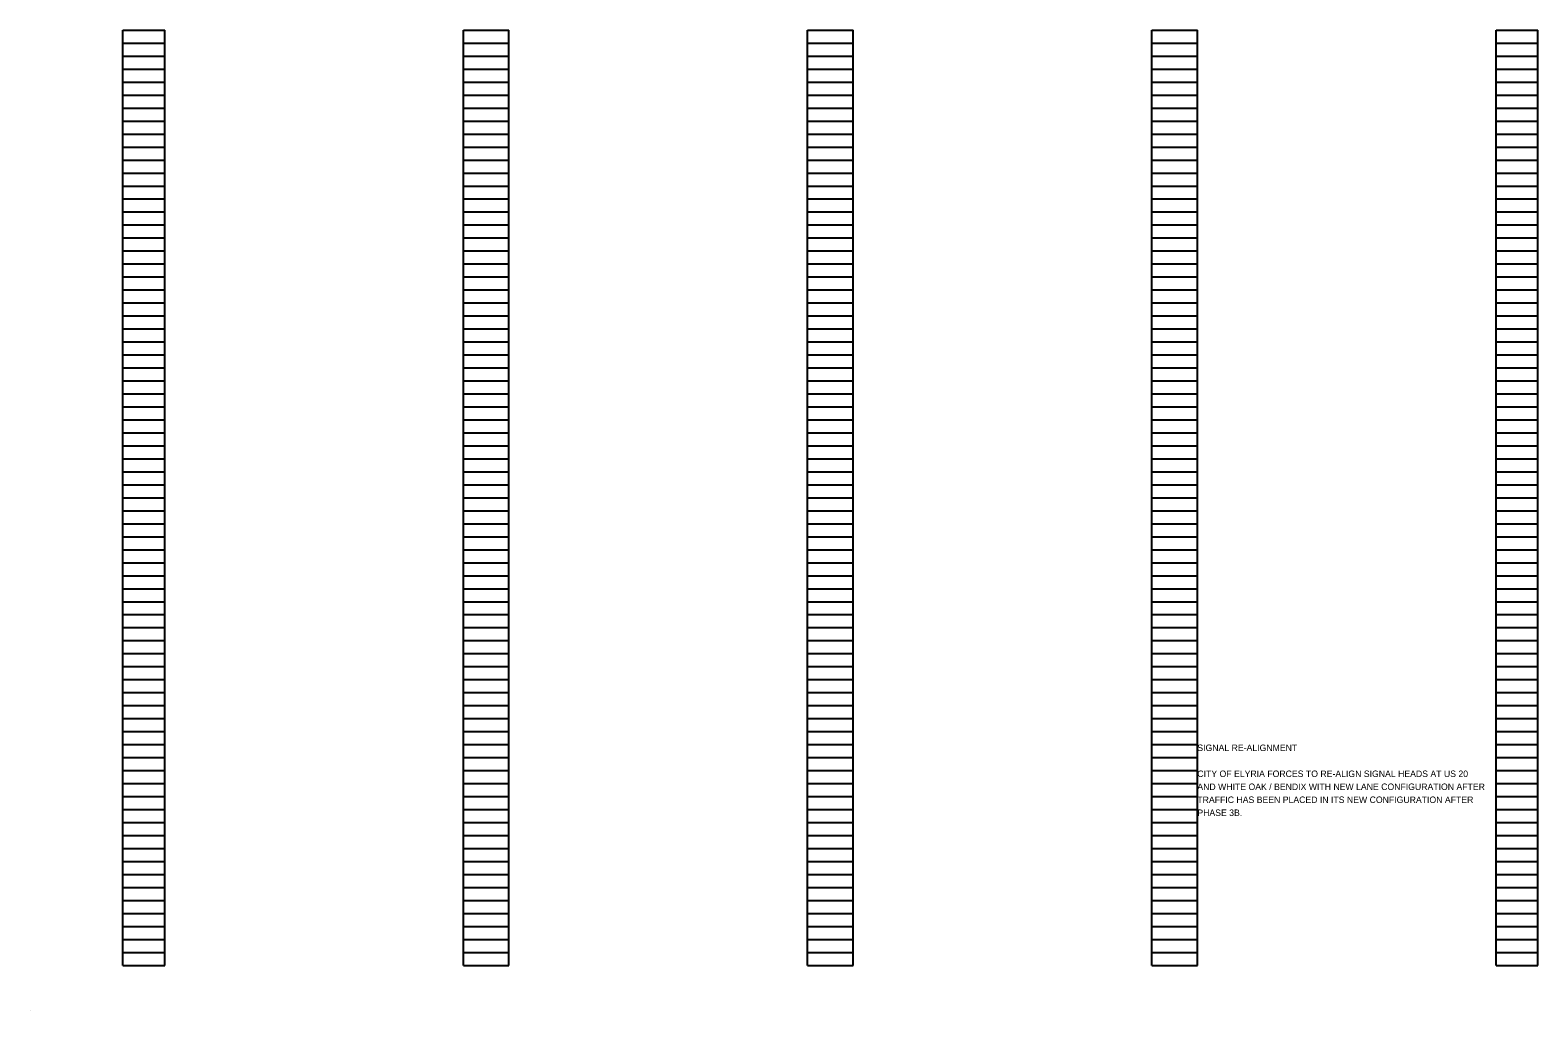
# Model space of a CAD drawing. Extents: x -12.2 to 34.1, y -24.5 to 43.2.
# Drawn here: x 1.62 to 34.12, y -24.51 to -3.37 of the extents above; entities that cross this region are included whole.
import ezdxf

# ---------------------------------------------------------------- set-up
doc = ezdxf.new("R2010")
doc.units = 0
doc.layers.add('SH_Data', color=7, linetype='Continuous')
doc.layers.add('SH_Text', color=7, linetype='Continuous')

msp = doc.modelspace()

# ---------------------------------------------------------------- linework, layer by layer
at = {"layer": 'SH_Data'}
for p, q in [((3.615, -23.528), (3.615, -3.368)), ((3.615, -3.368), (4.515, -3.368)), ((4.515, -23.528), (4.515, -3.368)), ((10.955, -23.528), (10.955, -3.368)), ((10.955, -3.368), (11.935, -3.368)), ((11.935, -23.528), (11.935, -3.368)), ((18.375, -23.528), (18.375, -3.368)), ((18.375, -3.368), (19.355, -3.368)), ((19.355, -23.528), (19.355, -3.368)), ((25.795, -23.528), (25.795, -3.368)), ((25.795, -3.368), (26.775, -3.368)), ((26.775, -23.528), (26.775, -3.368)), ((33.215, -23.528), (33.215, -3.368)), ((33.215, -3.368), (34.115, -3.368)), ((34.115, -23.528), (34.115, -3.368)), ((3.615, -3.648), (4.515, -3.648)), ((10.955, -3.648), (11.935, -3.648)), ((18.375, -3.648), (19.355, -3.648)), ((25.795, -3.648), (26.775, -3.648)), ((33.215, -3.648), (34.115, -3.648)), ((3.615, -3.928), (4.515, -3.928)), ((3.615, -4.208), (4.515, -4.208)), ((10.955, -3.928), (11.935, -3.928)), ((10.955, -4.208), (11.935, -4.208)), ((18.375, -3.928), (19.355, -3.928)), ((18.375, -4.208), (19.355, -4.208)), ((25.795, -3.928), (26.775, -3.928)), ((25.795, -4.208), (26.775, -4.208)), ((33.215, -3.928), (34.115, -3.928)), ((33.215, -4.208), (34.115, -4.208)), ((3.615, -4.488), (4.515, -4.488)), ((10.955, -4.488), (11.935, -4.488)), ((18.375, -4.488), (19.355, -4.488)), ((25.795, -4.488), (26.775, -4.488)), ((33.215, -4.488), (34.115, -4.488)), ((3.615, -4.768), (4.515, -4.768)), ((10.955, -4.768), (11.935, -4.768)), ((18.375, -4.768), (19.355, -4.768)), ((25.795, -4.768), (26.775, -4.768)), ((33.215, -4.768), (34.115, -4.768)), ((3.615, -5.048), (4.515, -5.048)), ((10.955, -5.048), (11.935, -5.048)), ((18.375, -5.048), (19.355, -5.048)), ((25.795, -5.048), (26.775, -5.048)), ((33.215, -5.048), (34.115, -5.048)), ((3.615, -5.328), (4.515, -5.328)), ((10.955, -5.328), (11.935, -5.328)), ((18.375, -5.328), (19.355, -5.328)), ((25.795, -5.328), (26.775, -5.328)), ((33.215, -5.328), (34.115, -5.328)), ((3.615, -5.608), (4.515, -5.608)), ((10.955, -5.608), (11.935, -5.608)), ((18.375, -5.608), (19.355, -5.608)), ((25.795, -5.608), (26.775, -5.608)), ((33.215, -5.608), (34.115, -5.608)), ((3.615, -5.888), (4.515, -5.888)), ((3.615, -6.168), (4.515, -6.168)), ((10.955, -5.888), (11.935, -5.888)), ((10.955, -6.168), (11.935, -6.168)), ((18.375, -5.888), (19.355, -5.888)), ((18.375, -6.168), (19.355, -6.168)), ((25.795, -5.888), (26.775, -5.888)), ((25.795, -6.168), (26.775, -6.168)), ((33.215, -5.888), (34.115, -5.888)), ((33.215, -6.168), (34.115, -6.168)), ((3.615, -6.448), (4.515, -6.448)), ((10.955, -6.448), (11.935, -6.448)), ((18.375, -6.448), (19.355, -6.448)), ((25.795, -6.448), (26.775, -6.448)), ((33.215, -6.448), (34.115, -6.448)), ((3.615, -6.728), (4.515, -6.728)), ((10.955, -6.728), (11.935, -6.728)), ((18.375, -6.728), (19.355, -6.728)), ((25.795, -6.728), (26.775, -6.728)), ((33.215, -6.728), (34.115, -6.728)), ((3.615, -7.008), (4.515, -7.008)), ((10.955, -7.008), (11.935, -7.008)), ((18.375, -7.008), (19.355, -7.008)), ((25.795, -7.008), (26.775, -7.008)), ((33.215, -7.008), (34.115, -7.008)), ((3.615, -7.288), (4.515, -7.288)), ((10.955, -7.288), (11.935, -7.288)), ((18.375, -7.288), (19.355, -7.288)), ((25.795, -7.288), (26.775, -7.288)), ((33.215, -7.288), (34.115, -7.288)), ((3.615, -7.568), (4.515, -7.568)), ((10.955, -7.568), (11.935, -7.568)), ((18.375, -7.568), (19.355, -7.568)), ((25.795, -7.568), (26.775, -7.568)), ((33.215, -7.568), (34.115, -7.568)), ((3.615, -7.848), (4.515, -7.848)), ((10.955, -7.848), (11.935, -7.848)), ((18.375, -7.848), (19.355, -7.848)), ((25.795, -7.848), (26.775, -7.848)), ((33.215, -7.848), (34.115, -7.848)), ((3.615, -8.128), (4.515, -8.128)), ((3.615, -8.408), (4.515, -8.408)), ((10.955, -8.128), (11.935, -8.128)), ((10.955, -8.408), (11.935, -8.408)), ((18.375, -8.128), (19.355, -8.128)), ((18.375, -8.408), (19.355, -8.408)), ((25.795, -8.128), (26.775, -8.128)), ((25.795, -8.408), (26.775, -8.408)), ((33.215, -8.128), (34.115, -8.128)), ((33.215, -8.408), (34.115, -8.408)), ((3.615, -8.688), (4.515, -8.688)), ((10.955, -8.688), (11.935, -8.688)), ((18.375, -8.688), (19.355, -8.688)), ((25.795, -8.688), (26.775, -8.688)), ((33.215, -8.688), (34.115, -8.688)), ((3.615, -8.968), (4.515, -8.968)), ((10.955, -8.968), (11.935, -8.968)), ((18.375, -8.968), (19.355, -8.968)), ((25.795, -8.968), (26.775, -8.968)), ((33.215, -8.968), (34.115, -8.968)), ((3.615, -9.248), (4.515, -9.248)), ((10.955, -9.248), (11.935, -9.248)), ((18.375, -9.248), (19.355, -9.248)), ((25.795, -9.248), (26.775, -9.248)), ((33.215, -9.248), (34.115, -9.248)), ((3.615, -9.528), (4.515, -9.528)), ((10.955, -9.528), (11.935, -9.528)), ((18.375, -9.528), (19.355, -9.528)), ((25.795, -9.528), (26.775, -9.528)), ((33.215, -9.528), (34.115, -9.528)), ((3.615, -9.808), (4.515, -9.808)), ((10.955, -9.808), (11.935, -9.808)), ((18.375, -9.808), (19.355, -9.808)), ((25.795, -9.808), (26.775, -9.808)), ((33.215, -9.808), (34.115, -9.808)), ((3.615, -10.088), (4.515, -10.088)), ((3.615, -10.368), (4.515, -10.368)), ((10.955, -10.088), (11.935, -10.088)), ((10.955, -10.368), (11.935, -10.368)), ((18.375, -10.088), (19.355, -10.088)), ((18.375, -10.368), (19.355, -10.368)), ((25.795, -10.088), (26.775, -10.088)), ((25.795, -10.368), (26.775, -10.368)), ((33.215, -10.088), (34.115, -10.088)), ((33.215, -10.368), (34.115, -10.368)), ((3.615, -10.648), (4.515, -10.648)), ((10.955, -10.648), (11.935, -10.648)), ((18.375, -10.648), (19.355, -10.648)), ((25.795, -10.648), (26.775, -10.648)), ((33.215, -10.648), (34.115, -10.648)), ((3.615, -10.928), (4.515, -10.928)), ((10.955, -10.928), (11.935, -10.928)), ((18.375, -10.928), (19.355, -10.928)), ((25.795, -10.928), (26.775, -10.928)), ((33.215, -10.928), (34.115, -10.928)), ((3.615, -11.208), (4.515, -11.208)), ((10.955, -11.208), (11.935, -11.208)), ((18.375, -11.208), (19.355, -11.208)), ((25.795, -11.208), (26.775, -11.208)), ((33.215, -11.208), (34.115, -11.208)), ((3.615, -11.488), (4.515, -11.488)), ((10.955, -11.488), (11.935, -11.488)), ((18.375, -11.488), (19.355, -11.488)), ((25.795, -11.488), (26.775, -11.488)), ((33.215, -11.488), (34.115, -11.488)), ((3.615, -11.768), (4.515, -11.768)), ((10.955, -11.768), (11.935, -11.768)), ((18.375, -11.768), (19.355, -11.768)), ((25.795, -11.768), (26.775, -11.768)), ((33.215, -11.768), (34.115, -11.768)), ((3.615, -12.048), (4.515, -12.048)), ((3.615, -12.328), (4.515, -12.328)), ((10.955, -12.048), (11.935, -12.048)), ((10.955, -12.328), (11.935, -12.328)), ((18.375, -12.048), (19.355, -12.048)), ((18.375, -12.328), (19.355, -12.328)), ((25.795, -12.048), (26.775, -12.048)), ((25.795, -12.328), (26.775, -12.328)), ((33.215, -12.048), (34.115, -12.048)), ((33.215, -12.328), (34.115, -12.328)), ((3.615, -12.608), (4.515, -12.608)), ((10.955, -12.608), (11.935, -12.608)), ((18.375, -12.608), (19.355, -12.608)), ((25.795, -12.608), (26.775, -12.608)), ((33.215, -12.608), (34.115, -12.608)), ((3.615, -12.888), (4.515, -12.888)), ((10.955, -12.888), (11.935, -12.888)), ((18.375, -12.888), (19.355, -12.888)), ((25.795, -12.888), (26.775, -12.888)), ((33.215, -12.888), (34.115, -12.888)), ((3.615, -13.168), (4.515, -13.168)), ((10.955, -13.168), (11.935, -13.168)), ((18.375, -13.168), (19.355, -13.168)), ((25.795, -13.168), (26.775, -13.168)), ((33.215, -13.168), (34.115, -13.168)), ((3.615, -13.448), (4.515, -13.448)), ((10.955, -13.448), (11.935, -13.448)), ((18.375, -13.448), (19.355, -13.448)), ((25.795, -13.448), (26.775, -13.448)), ((33.215, -13.448), (34.115, -13.448)), ((3.615, -13.728), (4.515, -13.728)), ((10.955, -13.728), (11.935, -13.728)), ((18.375, -13.728), (19.355, -13.728)), ((25.795, -13.728), (26.775, -13.728)), ((33.215, -13.728), (34.115, -13.728)), ((3.615, -14.008), (4.515, -14.008)), ((3.615, -14.288), (4.515, -14.288)), ((10.955, -14.008), (11.935, -14.008)), ((10.955, -14.288), (11.935, -14.288)), ((18.375, -14.008), (19.355, -14.008)), ((18.375, -14.288), (19.355, -14.288)), ((25.795, -14.008), (26.775, -14.008)), ((25.795, -14.288), (26.775, -14.288)), ((33.215, -14.008), (34.115, -14.008)), ((33.215, -14.288), (34.115, -14.288)), ((3.615, -14.568), (4.515, -14.568)), ((10.955, -14.568), (11.935, -14.568)), ((18.375, -14.568), (19.355, -14.568)), ((25.795, -14.568), (26.775, -14.568)), ((33.215, -14.568), (34.115, -14.568)), ((3.615, -14.848), (4.515, -14.848)), ((10.955, -14.848), (11.935, -14.848)), ((18.375, -14.848), (19.355, -14.848)), ((25.795, -14.848), (26.775, -14.848)), ((33.215, -14.848), (34.115, -14.848)), ((3.615, -15.128), (4.515, -15.128)), ((10.955, -15.128), (11.935, -15.128)), ((18.375, -15.128), (19.355, -15.128)), ((25.795, -15.128), (26.775, -15.128)), ((33.215, -15.128), (34.115, -15.128)), ((3.615, -15.408), (4.515, -15.408)), ((10.955, -15.408), (11.935, -15.408)), ((18.375, -15.408), (19.355, -15.408)), ((25.795, -15.408), (26.775, -15.408)), ((33.215, -15.408), (34.115, -15.408)), ((3.615, -15.688), (4.515, -15.688)), ((10.955, -15.688), (11.935, -15.688)), ((18.375, -15.688), (19.355, -15.688)), ((25.795, -15.688), (26.775, -15.688)), ((33.215, -15.688), (34.115, -15.688)), ((3.615, -15.968), (4.515, -15.968)), ((3.615, -16.248), (4.515, -16.248)), ((10.955, -15.968), (11.935, -15.968)), ((10.955, -16.248), (11.935, -16.248)), ((18.375, -15.968), (19.355, -15.968)), ((18.375, -16.248), (19.355, -16.248)), ((25.795, -15.968), (26.775, -15.968)), ((25.795, -16.248), (26.775, -16.248)), ((33.215, -15.968), (34.115, -15.968)), ((33.215, -16.248), (34.115, -16.248)), ((3.615, -16.528), (4.515, -16.528)), ((10.955, -16.528), (11.935, -16.528)), ((18.375, -16.528), (19.355, -16.528)), ((25.795, -16.528), (26.775, -16.528)), ((33.215, -16.528), (34.115, -16.528)), ((3.615, -16.808), (4.515, -16.808)), ((10.955, -16.808), (11.935, -16.808)), ((18.375, -16.808), (19.355, -16.808)), ((25.795, -16.808), (26.775, -16.808)), ((33.215, -16.808), (34.115, -16.808)), ((3.615, -17.088), (4.515, -17.088)), ((10.955, -17.088), (11.935, -17.088)), ((18.375, -17.088), (19.355, -17.088)), ((25.795, -17.088), (26.775, -17.088)), ((33.215, -17.088), (34.115, -17.088)), ((3.615, -17.368), (4.515, -17.368)), ((10.955, -17.368), (11.935, -17.368)), ((18.375, -17.368), (19.355, -17.368)), ((25.795, -17.368), (26.775, -17.368)), ((33.215, -17.368), (34.115, -17.368)), ((3.615, -17.648), (4.515, -17.648)), ((10.955, -17.648), (11.935, -17.648)), ((18.375, -17.648), (19.355, -17.648)), ((25.795, -17.648), (26.775, -17.648)), ((33.215, -17.648), (34.115, -17.648)), ((3.615, -17.928), (4.515, -17.928)), ((10.955, -17.928), (11.935, -17.928)), ((18.375, -17.928), (19.355, -17.928)), ((25.795, -17.928), (26.775, -17.928)), ((33.215, -17.928), (34.115, -17.928)), ((3.615, -18.208), (4.515, -18.208)), ((3.615, -18.488), (4.515, -18.488)), ((10.955, -18.208), (11.935, -18.208)), ((10.955, -18.488), (11.935, -18.488)), ((18.375, -18.208), (19.355, -18.208)), ((18.375, -18.488), (19.355, -18.488)), ((25.795, -18.208), (26.775, -18.208)), ((25.795, -18.488), (26.775, -18.488)), ((33.215, -18.208), (34.115, -18.208)), ((33.215, -18.488), (34.115, -18.488)), ((3.615, -18.768), (4.515, -18.768)), ((10.955, -18.768), (11.935, -18.768)), ((18.375, -18.768), (19.355, -18.768)), ((25.795, -18.768), (26.775, -18.768)), ((33.215, -18.768), (34.115, -18.768)), ((3.615, -19.048), (4.515, -19.048)), ((10.955, -19.048), (11.935, -19.048)), ((18.375, -19.048), (19.355, -19.048)), ((25.795, -19.048), (26.775, -19.048)), ((33.215, -19.048), (34.115, -19.048)), ((3.615, -19.328), (4.515, -19.328)), ((10.955, -19.328), (11.935, -19.328)), ((18.375, -19.328), (19.355, -19.328)), ((25.795, -19.328), (26.775, -19.328)), ((33.215, -19.328), (34.115, -19.328)), ((3.615, -19.608), (4.515, -19.608)), ((10.955, -19.608), (11.935, -19.608)), ((18.375, -19.608), (19.355, -19.608)), ((25.795, -19.608), (26.775, -19.608)), ((33.215, -19.608), (34.115, -19.608)), ((3.615, -19.888), (4.515, -19.888)), ((10.955, -19.888), (11.935, -19.888)), ((18.375, -19.888), (19.355, -19.888)), ((25.795, -19.888), (26.775, -19.888)), ((33.215, -19.888), (34.115, -19.888)), ((3.615, -20.168), (4.515, -20.168)), ((3.615, -20.448), (4.515, -20.448)), ((10.955, -20.168), (11.935, -20.168)), ((10.955, -20.448), (11.935, -20.448)), ((18.375, -20.168), (19.355, -20.168)), ((18.375, -20.448), (19.355, -20.448)), ((25.795, -20.168), (26.775, -20.168)), ((25.795, -20.448), (26.775, -20.448)), ((33.215, -20.168), (34.115, -20.168)), ((33.215, -20.448), (34.115, -20.448)), ((3.615, -20.728), (4.515, -20.728)), ((10.955, -20.728), (11.935, -20.728)), ((18.375, -20.728), (19.355, -20.728)), ((25.795, -20.728), (26.775, -20.728)), ((33.215, -20.728), (34.115, -20.728)), ((3.615, -21.008), (4.515, -21.008)), ((10.955, -21.008), (11.935, -21.008)), ((18.375, -21.008), (19.355, -21.008)), ((25.795, -21.008), (26.775, -21.008)), ((33.215, -21.008), (34.115, -21.008)), ((3.615, -21.288), (4.515, -21.288)), ((10.955, -21.288), (11.935, -21.288)), ((18.375, -21.288), (19.355, -21.288)), ((25.795, -21.288), (26.775, -21.288)), ((33.215, -21.288), (34.115, -21.288)), ((3.615, -21.568), (4.515, -21.568)), ((10.955, -21.568), (11.935, -21.568)), ((18.375, -21.568), (19.355, -21.568)), ((25.795, -21.568), (26.775, -21.568)), ((33.215, -21.568), (34.115, -21.568)), ((3.615, -21.848), (4.515, -21.848)), ((10.955, -21.848), (11.935, -21.848)), ((18.375, -21.848), (19.355, -21.848)), ((25.795, -21.848), (26.775, -21.848)), ((33.215, -21.848), (34.115, -21.848)), ((3.615, -22.128), (4.515, -22.128)), ((3.615, -22.408), (4.515, -22.408)), ((10.955, -22.128), (11.935, -22.128)), ((10.955, -22.408), (11.935, -22.408)), ((18.375, -22.128), (19.355, -22.128)), ((18.375, -22.408), (19.355, -22.408)), ((25.795, -22.128), (26.775, -22.128)), ((25.795, -22.408), (26.775, -22.408)), ((33.215, -22.128), (34.115, -22.128)), ((33.215, -22.408), (34.115, -22.408)), ((3.615, -22.688), (4.515, -22.688)), ((10.955, -22.688), (11.935, -22.688)), ((18.375, -22.688), (19.355, -22.688)), ((25.795, -22.688), (26.775, -22.688)), ((33.215, -22.688), (34.115, -22.688)), ((3.615, -22.968), (4.515, -22.968)), ((10.955, -22.968), (11.935, -22.968)), ((18.375, -22.968), (19.355, -22.968)), ((25.795, -22.968), (26.775, -22.968)), ((33.215, -22.968), (34.115, -22.968)), ((3.615, -23.248), (4.515, -23.248)), ((10.955, -23.248), (11.935, -23.248)), ((18.375, -23.248), (19.355, -23.248)), ((25.795, -23.248), (26.775, -23.248)), ((33.215, -23.248), (34.115, -23.248)), ((3.615, -23.528), (4.515, -23.528)), ((10.955, -23.528), (11.935, -23.528)), ((18.375, -23.528), (19.355, -23.528)), ((25.795, -23.528), (26.775, -23.528)), ((33.215, -23.528), (34.115, -23.528)), ((1.615, -24.508), (1.615, -24.508))]:
    msp.add_line(p, q, dxfattribs=at)

# ---------------------------------------------------------------- texts
at = {"layer": 'SH_Text'}
for s, p in [('SIGNAL RE-ALIGNMENT', (26.775, -18.908)), ('CITY OF ELYRIA FORCES TO RE-ALIGN SIGNAL HEADS AT US 20 ', (26.775, -19.468)), ('AND WHITE OAK / BENDIX WITH NEW LANE CONFIGURATION AFTER ', (26.775, -19.748)), ('TRAFFIC HAS BEEN PLACED IN ITS NEW CONFIGURATION AFTER ', (26.775, -20.028)), ('PHASE 3B.', (26.775, -20.308))]:
    msp.add_text(s, height=0.14, dxfattribs=at).set_placement(p)

doc.saveas('drawing.dxf')
